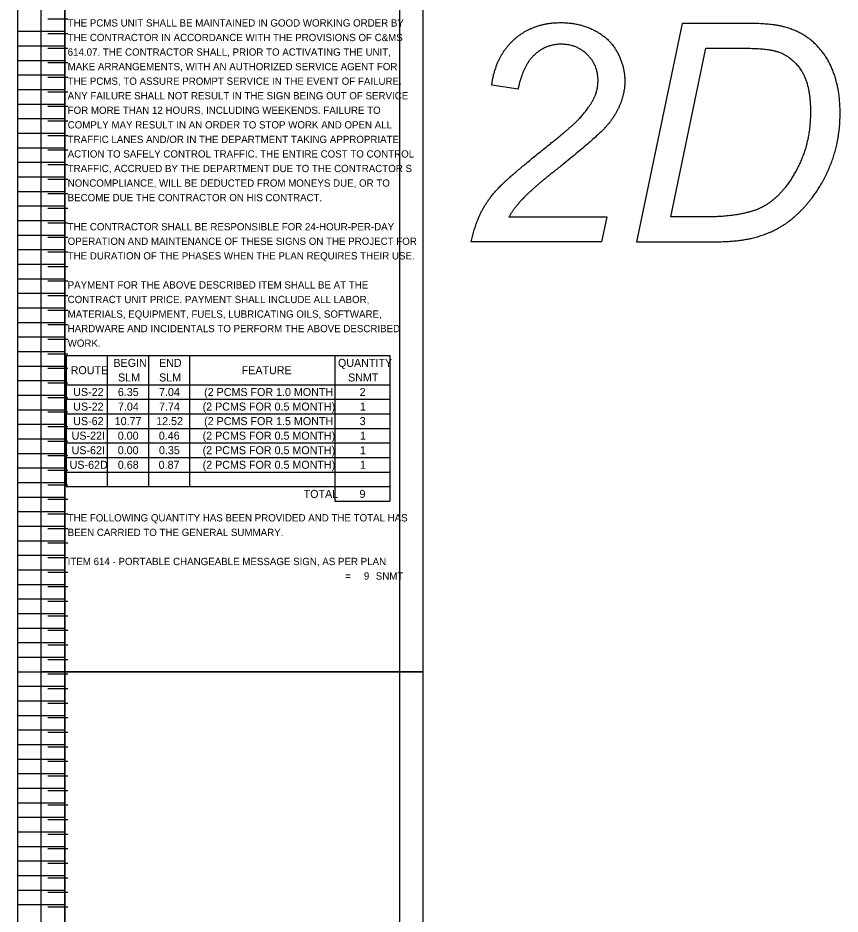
# Model space of a CAD drawing. Extents: x 12522 to 13018, y 1124 to 1902.
# Drawn here: x 12563.34 to 12579.16, y 1683.85 to 1701.09 of the extents above; entities that cross this region are included whole.
import ezdxf

# ---------------------------------------------------------------- set-up
doc = ezdxf.new("R2010")
doc.units = 0
for name, color, linetype in [('SC_Scratch1', 7, 'Continuous'), ('SH_Data', 7, 'Continuous'), ('SH_Text', 7, 'Continuous')]:
    doc.layers.add(name, color=color, linetype=linetype)

msp = doc.modelspace()

# ---------------------------------------------------------------- linework, layer by layer
at = {"layer": 'SC_Scratch1'}
for p, q in [((12563.336, 1688.511), (12563.336, 1708.671)), ((12563.336, 1688.511), (12563.336, 1708.671)), ((12564.236, 1688.511), (12564.236, 1708.671)), ((12564.236, 1708.671), (12564.236, 1688.511)), ((12564.236, 1688.511), (12564.236, 1708.671)), ((12564.293, 1701.061), (12563.909, 1701.061)), ((12563.336, 1700.831), (12564.236, 1700.831)), ((12563.336, 1700.831), (12564.236, 1700.831)), ((12564.293, 1700.781), (12563.909, 1700.781)), ((12563.336, 1700.551), (12564.236, 1700.551)), ((12563.336, 1700.551), (12564.236, 1700.551)), ((12564.293, 1700.501), (12563.909, 1700.501)), ((12563.336, 1700.271), (12564.236, 1700.271)), ((12563.336, 1700.271), (12564.236, 1700.271)), ((12564.293, 1700.221), (12563.909, 1700.221)), ((12563.336, 1699.991), (12564.236, 1699.991)), ((12563.336, 1699.991), (12564.236, 1699.991)), ((12564.293, 1699.941), (12563.909, 1699.941)), ((12563.336, 1699.711), (12564.236, 1699.711)), ((12563.336, 1699.711), (12564.236, 1699.711)), ((12564.293, 1699.661), (12563.909, 1699.661)), ((12572.959, 1699.719), (12572.453, 1699.794)), ((12572.959, 1699.719), (12572.453, 1699.794)), ((12563.336, 1699.431), (12564.236, 1699.431)), ((12563.336, 1699.431), (12564.236, 1699.431)), ((12564.293, 1699.381), (12563.909, 1699.381)), ((12563.336, 1699.151), (12564.236, 1699.151)), ((12563.336, 1699.151), (12564.236, 1699.151)), ((12564.293, 1699.101), (12563.909, 1699.101)), ((12563.336, 1698.871), (12564.236, 1698.871)), ((12563.336, 1698.871), (12564.236, 1698.871)), ((12564.293, 1698.821), (12563.909, 1698.821)), ((12563.336, 1698.591), (12564.236, 1698.591)), ((12563.336, 1698.591), (12564.236, 1698.591)), ((12564.293, 1698.541), (12563.909, 1698.541)), ((12563.336, 1698.311), (12564.236, 1698.311)), ((12563.336, 1698.311), (12564.236, 1698.311)), ((12564.293, 1698.261), (12563.909, 1698.261)), ((12563.336, 1698.031), (12564.236, 1698.031)), ((12563.336, 1698.031), (12564.236, 1698.031)), ((12564.293, 1697.981), (12563.909, 1697.981)), ((12563.336, 1697.751), (12564.236, 1697.751)), ((12563.336, 1697.751), (12564.236, 1697.751)), ((12564.293, 1697.701), (12563.909, 1697.701)), ((12563.336, 1697.471), (12564.236, 1697.471)), ((12563.336, 1697.471), (12564.236, 1697.471)), ((12564.293, 1697.421), (12563.909, 1697.421)), ((12563.336, 1697.191), (12564.236, 1697.191)), ((12563.336, 1697.191), (12564.236, 1697.191)), ((12564.293, 1697.141), (12563.909, 1697.141)), ((12563.336, 1696.911), (12564.236, 1696.911)), ((12563.336, 1696.911), (12564.236, 1696.911)), ((12564.293, 1696.861), (12563.909, 1696.861)), ((12563.336, 1696.631), (12564.236, 1696.631)), ((12563.336, 1696.631), (12564.236, 1696.631)), ((12564.293, 1696.581), (12563.909, 1696.581)), ((12563.336, 1696.351), (12564.236, 1696.351)), ((12563.336, 1696.351), (12564.236, 1696.351)), ((12564.293, 1696.301), (12563.909, 1696.301)), ((12563.336, 1696.071), (12564.236, 1696.071)), ((12563.336, 1696.071), (12564.236, 1696.071)), ((12564.293, 1696.021), (12563.909, 1696.021)), ((12563.336, 1695.791), (12564.236, 1695.791)), ((12563.336, 1695.791), (12564.236, 1695.791)), ((12564.293, 1695.741), (12563.909, 1695.741)), ((12563.336, 1695.511), (12564.236, 1695.511)), ((12563.336, 1695.511), (12564.236, 1695.511)), ((12564.293, 1695.461), (12563.909, 1695.461)), ((12563.336, 1695.231), (12564.236, 1695.231)), ((12563.336, 1695.231), (12564.236, 1695.231)), ((12564.293, 1695.181), (12563.909, 1695.181)), ((12563.336, 1694.951), (12564.236, 1694.951)), ((12563.336, 1694.951), (12564.236, 1694.951)), ((12564.293, 1694.901), (12563.909, 1694.901)), ((12563.336, 1694.671), (12564.236, 1694.671)), ((12563.336, 1694.671), (12564.236, 1694.671)), ((12564.293, 1694.621), (12563.909, 1694.621)), ((12563.336, 1694.391), (12564.236, 1694.391)), ((12563.336, 1694.391), (12564.236, 1694.391)), ((12564.293, 1694.341), (12563.909, 1694.341)), ((12563.336, 1694.111), (12564.236, 1694.111)), ((12563.336, 1694.111), (12564.236, 1694.111)), ((12564.293, 1694.061), (12563.909, 1694.061)), ((12563.336, 1693.831), (12564.236, 1693.831)), ((12563.336, 1693.831), (12564.236, 1693.831)), ((12564.293, 1693.781), (12563.909, 1693.781)), ((12563.336, 1693.551), (12564.236, 1693.551)), ((12563.336, 1693.551), (12564.236, 1693.551)), ((12564.293, 1693.501), (12563.909, 1693.501)), ((12563.336, 1693.271), (12564.236, 1693.271)), ((12563.336, 1693.271), (12564.236, 1693.271)), ((12564.293, 1693.221), (12563.909, 1693.221)), ((12563.336, 1692.991), (12564.236, 1692.991)), ((12563.336, 1692.991), (12564.236, 1692.991)), ((12564.293, 1692.941), (12563.909, 1692.941)), ((12563.336, 1692.711), (12564.236, 1692.711)), ((12563.336, 1692.711), (12564.236, 1692.711)), ((12564.293, 1692.661), (12563.909, 1692.661)), ((12563.336, 1692.431), (12564.236, 1692.431)), ((12563.336, 1692.431), (12564.236, 1692.431)), ((12564.293, 1692.381), (12563.909, 1692.381)), ((12563.336, 1692.151), (12564.236, 1692.151)), ((12563.336, 1692.151), (12564.236, 1692.151)), ((12564.293, 1692.101), (12563.909, 1692.101)), ((12563.336, 1691.871), (12564.236, 1691.871)), ((12563.336, 1691.871), (12564.236, 1691.871)), ((12564.293, 1691.821), (12563.909, 1691.821)), ((12563.336, 1691.591), (12564.236, 1691.591)), ((12563.336, 1691.591), (12564.236, 1691.591)), ((12564.293, 1691.541), (12563.909, 1691.541)), ((12563.336, 1691.311), (12564.236, 1691.311)), ((12563.336, 1691.311), (12564.236, 1691.311)), ((12564.293, 1691.261), (12563.909, 1691.261)), ((12563.336, 1691.031), (12564.236, 1691.031)), ((12563.336, 1691.031), (12564.236, 1691.031)), ((12564.293, 1690.981), (12563.909, 1690.981)), ((12563.336, 1690.751), (12564.236, 1690.751)), ((12563.336, 1690.751), (12564.236, 1690.751)), ((12564.293, 1690.701), (12563.909, 1690.701)), ((12563.336, 1690.471), (12564.236, 1690.471)), ((12563.336, 1690.471), (12564.236, 1690.471)), ((12564.293, 1690.421), (12563.909, 1690.421)), ((12563.336, 1690.191), (12564.236, 1690.191)), ((12563.336, 1690.191), (12564.236, 1690.191)), ((12564.293, 1690.141), (12563.909, 1690.141)), ((12563.336, 1689.911), (12564.236, 1689.911)), ((12563.336, 1689.911), (12564.236, 1689.911)), ((12564.293, 1689.861), (12563.909, 1689.861)), ((12563.336, 1689.631), (12564.236, 1689.631)), ((12563.336, 1689.631), (12564.236, 1689.631)), ((12564.293, 1689.581), (12563.909, 1689.581)), ((12563.336, 1689.351), (12564.236, 1689.351)), ((12563.336, 1689.351), (12564.236, 1689.351)), ((12564.293, 1689.301), (12563.909, 1689.301)), ((12563.336, 1689.071), (12564.236, 1689.071)), ((12563.336, 1689.071), (12564.236, 1689.071)), ((12564.293, 1689.021), (12563.909, 1689.021)), ((12563.336, 1688.791), (12564.236, 1688.791)), ((12563.336, 1688.791), (12564.236, 1688.791)), ((12564.293, 1688.741), (12563.909, 1688.741)), ((12563.336, 1688.511), (12564.236, 1688.511)), ((12563.336, 1668.351), (12563.336, 1688.511)), ((12563.336, 1688.511), (12564.236, 1688.511)), ((12563.336, 1688.511), (12564.236, 1688.511)), ((12563.336, 1668.351), (12563.336, 1688.511)), ((12563.336, 1688.511), (12564.236, 1688.511)), ((12564.293, 1688.461), (12563.909, 1688.461)), ((12564.236, 1668.351), (12564.236, 1688.511)), ((12564.236, 1688.511), (12564.236, 1668.351)), ((12564.236, 1668.351), (12564.236, 1688.511)), ((12563.336, 1688.231), (12564.236, 1688.231)), ((12563.336, 1688.231), (12564.236, 1688.231)), ((12564.293, 1688.181), (12563.909, 1688.181)), ((12563.336, 1687.951), (12564.236, 1687.951)), ((12563.336, 1687.951), (12564.236, 1687.951)), ((12564.293, 1687.901), (12563.909, 1687.901)), ((12563.336, 1687.671), (12564.236, 1687.671)), ((12563.336, 1687.671), (12564.236, 1687.671)), ((12564.293, 1687.621), (12563.909, 1687.621)), ((12563.336, 1687.391), (12564.236, 1687.391)), ((12563.336, 1687.391), (12564.236, 1687.391)), ((12564.293, 1687.341), (12563.909, 1687.341)), ((12563.336, 1687.111), (12564.236, 1687.111)), ((12563.336, 1687.111), (12564.236, 1687.111)), ((12564.293, 1687.061), (12563.909, 1687.061)), ((12563.336, 1686.831), (12564.236, 1686.831)), ((12563.336, 1686.831), (12564.236, 1686.831)), ((12564.293, 1686.781), (12563.909, 1686.781)), ((12563.336, 1686.551), (12564.236, 1686.551)), ((12563.336, 1686.551), (12564.236, 1686.551)), ((12564.293, 1686.501), (12563.909, 1686.501)), ((12563.336, 1686.271), (12564.236, 1686.271)), ((12563.336, 1686.271), (12564.236, 1686.271)), ((12564.293, 1686.221), (12563.909, 1686.221)), ((12563.336, 1685.991), (12564.236, 1685.991)), ((12563.336, 1685.991), (12564.236, 1685.991)), ((12564.293, 1685.941), (12563.909, 1685.941)), ((12563.336, 1685.711), (12564.236, 1685.711)), ((12563.336, 1685.711), (12564.236, 1685.711)), ((12564.293, 1685.661), (12563.909, 1685.661)), ((12563.336, 1685.431), (12564.236, 1685.431)), ((12563.336, 1685.431), (12564.236, 1685.431)), ((12564.293, 1685.381), (12563.909, 1685.381)), ((12563.336, 1685.151), (12564.236, 1685.151)), ((12563.336, 1685.151), (12564.236, 1685.151)), ((12564.293, 1685.101), (12563.909, 1685.101)), ((12563.336, 1684.871), (12564.236, 1684.871)), ((12563.336, 1684.871), (12564.236, 1684.871)), ((12564.293, 1684.821), (12563.909, 1684.821)), ((12563.336, 1684.591), (12564.236, 1684.591)), ((12563.336, 1684.591), (12564.236, 1684.591)), ((12564.293, 1684.541), (12563.909, 1684.541)), ((12563.336, 1684.311), (12564.236, 1684.311)), ((12563.336, 1684.311), (12564.236, 1684.311)), ((12564.293, 1684.261), (12563.909, 1684.261)), ((12563.336, 1684.031), (12564.236, 1684.031)), ((12563.336, 1684.031), (12564.236, 1684.031)), ((12564.293, 1683.981), (12563.909, 1683.981))]:
    msp.add_line(p, q, dxfattribs=at)
for points in [[(12563.786, 1708.671), (12571.126, 1708.671), (12571.126, 1688.511), (12563.786, 1688.511)], [(12564.236, 1708.671), (12570.676, 1708.671), (12570.676, 1688.511), (12564.236, 1688.511)], [(12564.236, 1708.671), (12570.676, 1708.671), (12570.676, 1688.511), (12564.236, 1688.511)], [(12563.786, 1688.511), (12571.126, 1688.511), (12571.126, 1668.351), (12563.786, 1668.351)], [(12564.236, 1688.511), (12570.676, 1688.511), (12570.676, 1668.351), (12564.236, 1668.351)], [(12564.236, 1688.511), (12570.676, 1688.511), (12570.676, 1668.351), (12564.236, 1668.351)]]:
    msp.add_lwpolyline(points, close=True, dxfattribs=at)
for points in [[(12577.382, 1700.981), (12576.115, 1700.981), (12575.238, 1696.781), (12576.752, 1696.781)], [(12577.382, 1700.981), (12576.115, 1700.981), (12575.238, 1696.781), (12576.752, 1696.781)], [(12576.563, 1697.258), (12575.897, 1697.258), (12576.575, 1700.504), (12577.319, 1700.504)], [(12576.563, 1697.258), (12575.897, 1697.258), (12576.575, 1700.504), (12577.319, 1700.504)], [(12572.785, 1697.258), (12574.665, 1697.258), (12574.565, 1696.781), (12572.06, 1696.781)], [(12572.785, 1697.258), (12574.665, 1697.258), (12574.565, 1696.781), (12572.06, 1696.781)]]:
    msp.add_lwpolyline(points, dxfattribs=at)
for points in [[(12572.887, 1700.675), (12573.247, 1700.997), (12573.782, 1700.997)], [(12572.887, 1700.675), (12573.247, 1700.997), (12573.782, 1700.997)], [(12573.782, 1700.997), (12574.141, 1700.997), (12574.431, 1700.848)], [(12573.782, 1700.997), (12574.141, 1700.997), (12574.431, 1700.848)], [(12574.431, 1700.848), (12574.722, 1700.699), (12574.868, 1700.43)], [(12574.431, 1700.848), (12574.722, 1700.699), (12574.868, 1700.43)], [(12578.079, 1700.915), (12577.838, 1700.981), (12577.382, 1700.981)], [(12578.079, 1700.915), (12577.838, 1700.981), (12577.382, 1700.981)], [(12578.666, 1700.598), (12578.423, 1700.826), (12578.079, 1700.915)], [(12578.666, 1700.598), (12578.423, 1700.826), (12578.079, 1700.915)], [(12572.453, 1699.794), (12572.528, 1700.352), (12572.887, 1700.675)], [(12572.453, 1699.794), (12572.528, 1700.352), (12572.887, 1700.675)], [(12573.791, 1700.581), (12573.495, 1700.581), (12573.274, 1700.376)], [(12573.791, 1700.581), (12573.495, 1700.581), (12573.274, 1700.376)], [(12574.294, 1700.379), (12574.089, 1700.581), (12573.791, 1700.581)], [(12574.294, 1700.379), (12574.089, 1700.581), (12573.791, 1700.581)], [(12577.319, 1700.504), (12577.75, 1700.504), (12577.954, 1700.438)], [(12577.319, 1700.504), (12577.75, 1700.504), (12577.954, 1700.438)], [(12579.033, 1700.03), (12578.91, 1700.371), (12578.666, 1700.598)], [(12579.033, 1700.03), (12578.91, 1700.371), (12578.666, 1700.598)], [(12573.274, 1700.376), (12573.054, 1700.171), (12572.959, 1699.719)], [(12573.274, 1700.376), (12573.054, 1700.171), (12572.959, 1699.719)], [(12574.499, 1699.888), (12574.499, 1700.177), (12574.294, 1700.379)], [(12574.499, 1699.888), (12574.499, 1700.177), (12574.294, 1700.379)], [(12574.868, 1700.43), (12575.014, 1700.161), (12575.014, 1699.874)], [(12574.868, 1700.43), (12575.014, 1700.161), (12575.014, 1699.874)], [(12577.954, 1700.438), (12578.23, 1700.349), (12578.409, 1700.076)], [(12577.954, 1700.438), (12578.23, 1700.349), (12578.409, 1700.076)], [(12578.409, 1700.076), (12578.587, 1699.802), (12578.587, 1699.292)], [(12578.409, 1700.076), (12578.587, 1699.802), (12578.587, 1699.292)], [(12579.157, 1699.265), (12579.157, 1699.689), (12579.033, 1700.03)], [(12579.157, 1699.265), (12579.157, 1699.689), (12579.033, 1700.03)], [(12574.433, 1699.57), (12574.499, 1699.716), (12574.499, 1699.888)], [(12574.433, 1699.57), (12574.499, 1699.716), (12574.499, 1699.888)], [(12575.014, 1699.874), (12575.014, 1699.456), (12574.716, 1699.069)], [(12575.014, 1699.874), (12575.014, 1699.456), (12574.716, 1699.069)], [(12574.121, 1699.132), (12574.335, 1699.356), (12574.433, 1699.57)], [(12574.121, 1699.132), (12574.335, 1699.356), (12574.433, 1699.57)], [(12578.587, 1699.292), (12578.587, 1698.834), (12578.456, 1698.474)], [(12578.587, 1699.292), (12578.587, 1698.834), (12578.456, 1698.474)], [(12573.564, 1698.654), (12573.971, 1698.978), (12574.121, 1699.132)], [(12573.564, 1698.654), (12573.971, 1698.978), (12574.121, 1699.132)], [(12579.003, 1698.341), (12579.157, 1698.758), (12579.157, 1699.265)], [(12579.003, 1698.341), (12579.157, 1698.758), (12579.157, 1699.265)], [(12574.716, 1699.069), (12574.533, 1698.829), (12573.639, 1698.122)], [(12574.716, 1699.069), (12574.533, 1698.829), (12573.639, 1698.122)], [(12572.659, 1697.891), (12572.894, 1698.119), (12573.564, 1698.654)], [(12572.659, 1697.891), (12572.894, 1698.119), (12573.564, 1698.654)], [(12578.456, 1698.474), (12578.326, 1698.115), (12578.107, 1697.834)], [(12578.456, 1698.474), (12578.326, 1698.115), (12578.107, 1697.834)], [(12578.602, 1697.607), (12578.85, 1697.924), (12579.003, 1698.341)], [(12578.602, 1697.607), (12578.85, 1697.924), (12579.003, 1698.341)], [(12573.639, 1698.122), (12573.255, 1697.819), (12573.067, 1697.624)], [(12573.639, 1698.122), (12573.255, 1697.819), (12573.067, 1697.624)], [(12572.282, 1697.41), (12572.424, 1697.664), (12572.659, 1697.891)], [(12572.282, 1697.41), (12572.424, 1697.664), (12572.659, 1697.891)], [(12578.107, 1697.834), (12577.941, 1697.622), (12577.737, 1697.493)], [(12578.107, 1697.834), (12577.941, 1697.622), (12577.737, 1697.493)], [(12573.067, 1697.624), (12572.879, 1697.43), (12572.785, 1697.258)], [(12573.067, 1697.624), (12572.879, 1697.43), (12572.785, 1697.258)], [(12578.083, 1697.112), (12578.354, 1697.291), (12578.602, 1697.607)], [(12578.083, 1697.112), (12578.354, 1697.291), (12578.602, 1697.607)], [(12572.06, 1696.781), (12572.14, 1697.156), (12572.282, 1697.41)], [(12572.06, 1696.781), (12572.14, 1697.156), (12572.282, 1697.41)], [(12577.737, 1697.493), (12577.582, 1697.393), (12577.364, 1697.341)], [(12577.737, 1697.493), (12577.582, 1697.393), (12577.364, 1697.341)], [(12577.364, 1697.341), (12577.014, 1697.258), (12576.563, 1697.258)], [(12577.364, 1697.341), (12577.014, 1697.258), (12576.563, 1697.258)], [(12577.443, 1696.847), (12577.812, 1696.933), (12578.083, 1697.112)], [(12577.443, 1696.847), (12577.812, 1696.933), (12578.083, 1697.112)], [(12576.752, 1696.781), (12577.162, 1696.781), (12577.443, 1696.847)], [(12576.752, 1696.781), (12577.162, 1696.781), (12577.443, 1696.847)]]:
    msp.add_open_spline(points, degree=2, dxfattribs=at)
at = {"layer": 'SH_Data'}
for p, q in [((12564.264, 1694.591), (12570.49, 1694.591)), ((12564.264, 1694.591), (12564.264, 1692.071)), ((12565.055, 1694.591), (12565.055, 1692.071)), ((12565.846, 1694.591), (12565.846, 1692.071)), ((12566.636, 1694.591), (12566.636, 1692.071)), ((12569.436, 1694.591), (12569.436, 1691.791)), ((12570.49, 1694.591), (12570.49, 1691.791)), ((12564.264, 1694.031), (12570.49, 1694.031)), ((12564.264, 1693.751), (12570.49, 1693.751)), ((12564.264, 1693.471), (12570.49, 1693.471)), ((12564.264, 1693.191), (12570.49, 1693.191)), ((12564.264, 1692.911), (12570.49, 1692.911)), ((12564.264, 1692.631), (12570.49, 1692.631)), ((12564.264, 1692.351), (12570.49, 1692.351)), ((12564.264, 1692.071), (12570.49, 1692.071)), ((12569.436, 1691.791), (12570.49, 1691.791))]:
    msp.add_line(p, q, dxfattribs=at)

# ---------------------------------------------------------------- texts
at = {"layer": 'SH_Text'}
for s, height, p in [('THE PCMS UNIT SHALL BE MAINTAINED IN GOOD WORKING ORDER BY ', 0.14, (12564.293, 1700.921)), ('THE CONTRACTOR IN ACCORDANCE WITH THE PROVISIONS OF C&MS ', 0.14, (12564.293, 1700.641)), ('614.07. THE CONTRACTOR SHALL, PRIOR TO ACTIVATING THE UNIT, ', 0.14, (12564.293, 1700.361)), ('MAKE ARRANGEMENTS, WITH AN AUTHORIZED SERVICE AGENT FOR ', 0.14, (12564.293, 1700.081)), ('THE PCMS, TO ASSURE PROMPT SERVICE IN THE EVENT OF FAILURE. ', 0.14, (12564.293, 1699.801)), ('ANY FAILURE SHALL NOT RESULT IN THE SIGN BEING OUT OF SERVICE ', 0.14, (12564.293, 1699.521)), ('FOR MORE THAN 12 HOURS, INCLUDING WEEKENDS. FAILURE TO ', 0.14, (12564.293, 1699.241)), ('COMPLY MAY RESULT IN AN ORDER TO STOP WORK AND OPEN ALL ', 0.14, (12564.293, 1698.961)), ('TRAFFIC LANES AND/OR IN THE DEPARTMENT TAKING APPROPRIATE ', 0.14, (12564.293, 1698.681)), ('ACTION TO SAFELY CONTROL TRAFFIC. THE ENTIRE COST TO CONTROL ', 0.14, (12564.293, 1698.401)), ('TRAFFIC, ACCRUED BY THE DEPARTMENT DUE TO THE CONTRACTOR S ', 0.14, (12564.293, 1698.121)), ('NONCOMPLIANCE, WILL BE DEDUCTED FROM MONEYS DUE, OR TO ', 0.14, (12564.293, 1697.841)), ('BECOME DUE THE CONTRACTOR ON HIS CONTRACT.', 0.14, (12564.293, 1697.561)), ('THE CONTRACTOR SHALL BE RESPONSIBLE FOR 24-HOUR-PER-DAY ', 0.14, (12564.293, 1697.001)), ('OPERATION AND MAINTENANCE OF THESE SIGNS ON THE PROJECT FOR ', 0.14, (12564.293, 1696.721)), ('THE DURATION OF THE PHASES WHEN THE PLAN REQUIRES THEIR USE. ', 0.14, (12564.293, 1696.441)), ('PAYMENT FOR THE ABOVE DESCRIBED ITEM SHALL BE AT THE ', 0.14, (12564.293, 1695.881)), ('CONTRACT UNIT PRICE. PAYMENT SHALL INCLUDE ALL LABOR, ', 0.14, (12564.293, 1695.601)), ('MATERIALS, EQUIPMENT, FUELS, LUBRICATING OILS, SOFTWARE, ', 0.14, (12564.293, 1695.321)), ('HARDWARE AND INCIDENTALS TO PERFORM THE ABOVE DESCRIBED ', 0.14, (12564.293, 1695.041)), ('WORK. ', 0.14, (12564.293, 1694.761)), ('BEGIN', 0.154, (12565.173, 1694.374)), ('END', 0.154, (12566.052, 1694.374)), ('QUANTITY', 0.154, (12569.495, 1694.374)), ('ROUTE', 0.154, (12564.351, 1694.234)), ('FEATURE', 0.154, (12567.642, 1694.234)), ('SLM', 0.154, (12565.263, 1694.094)), ('SLM', 0.154, (12566.053, 1694.094)), ('SNMT', 0.154, (12569.689, 1694.094)), ('US-22', 0.154, (12564.4, 1693.814)), ('6.35', 0.154, (12565.259, 1693.814)), ('7.04', 0.154, (12566.051, 1693.814)), ('(2 PCMS FOR 1.0 MONTH', 0.154, (12566.919, 1693.814)), ('2', 0.154, (12569.911, 1693.814)), ('US-22', 0.154, (12564.4, 1693.534)), ('7.04', 0.154, (12565.261, 1693.534)), ('7.74', 0.154, (12566.051, 1693.534)), ('(2 PCMS FOR 0.5 MONTH)', 0.154, (12566.89, 1693.534)), ('1', 0.154, (12569.918, 1693.534)), ('US-62', 0.154, (12564.4, 1693.254)), ('10.77', 0.154, (12565.198, 1693.254)), ('12.52', 0.154, (12565.996, 1693.254)), ('(2 PCMS FOR 1.5 MONTH', 0.154, (12566.919, 1693.254)), ('3', 0.154, (12569.912, 1693.254)), ('US-22I', 0.154, (12564.369, 1692.974)), ('0.00', 0.154, (12565.257, 1692.974)), ('0.46', 0.154, (12566.047, 1692.974)), ('(2 PCMS FOR 0.5 MONTH)', 0.154, (12566.89, 1692.974)), ('1', 0.154, (12569.918, 1692.974)), ('US-62I', 0.154, (12564.369, 1692.694)), ('0.00', 0.154, (12565.257, 1692.694)), ('0.35', 0.154, (12566.05, 1692.694)), ('(2 PCMS FOR 0.5 MONTH)', 0.154, (12566.89, 1692.694)), ('1', 0.154, (12569.918, 1692.694)), ('US-62D', 0.154, (12564.331, 1692.414)), ('0.68', 0.154, (12565.258, 1692.414)), ('0.87', 0.154, (12566.044, 1692.414)), ('(2 PCMS FOR 0.5 MONTH)', 0.154, (12566.89, 1692.414)), ('1', 0.154, (12569.918, 1692.414)), ('TOTAL', 0.154, (12568.834, 1691.854)), ('9', 0.154, (12569.909, 1691.854)), ('THE FOLLOWING QUANTITY HAS BEEN PROVIDED AND THE TOTAL HAS ', 0.14, (12564.293, 1691.401)), ('BEEN CARRIED TO THE GENERAL SUMMARY.', 0.14, (12564.293, 1691.121)), ('ITEM 614 - PORTABLE CHANGEABLE MESSAGE SIGN, AS PER PLAN', 0.14, (12564.293, 1690.561)), (' =', 0.14, (12569.58, 1690.281)), ('9', 0.14, (12569.993, 1690.281)), ('SNMT', 0.14, (12570.222, 1690.281))]:
    msp.add_text(s, height=height, dxfattribs=at).set_placement(p)

doc.saveas('drawing.dxf')
